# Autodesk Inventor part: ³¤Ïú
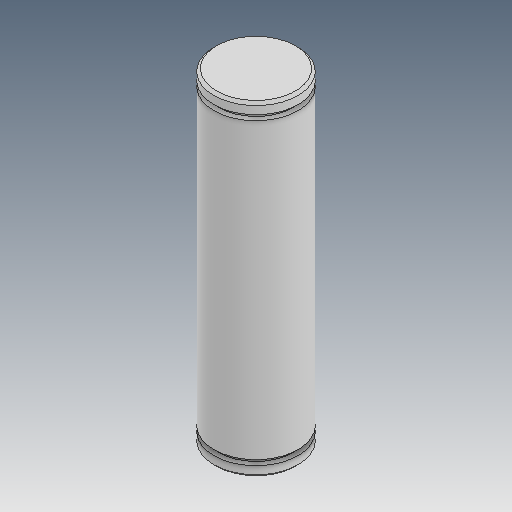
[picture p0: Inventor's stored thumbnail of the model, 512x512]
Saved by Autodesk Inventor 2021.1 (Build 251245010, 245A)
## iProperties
Created: 2019-04
Part Number: ³¤Ïú
Material: Ogólny
Document SubType Name: Modeling
Designer: user
Density: 1 g/cm^3
Appearance: Domyślna
Author: user
Revision Number: ÈÎºÎ
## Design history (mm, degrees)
feature "ÊäÈë1"
node "Bryła1"
